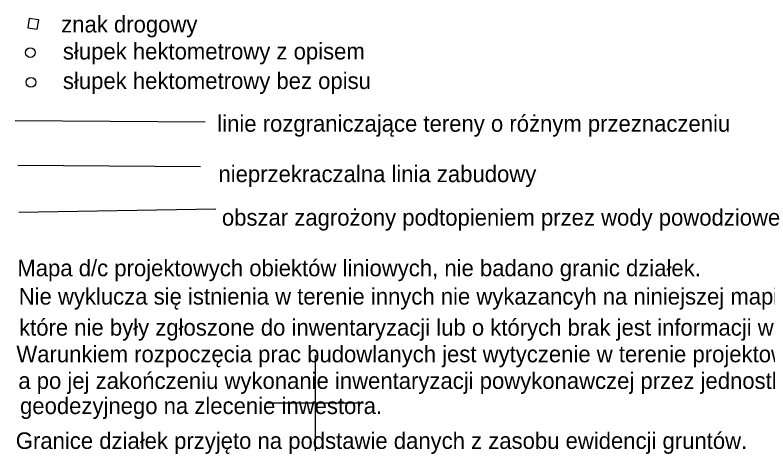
# Model space of a CAD drawing. Extents: x 6596400 to 6597200, y 5539751 to 5540251.
# Drawn here: x 6596634.31 to 6596673.62, y 5540048.34 to 5540071.24 of the extents above; entities that cross this region are included whole.
import ezdxf

# ---------------------------------------------------------------- set-up
doc = ezdxf.new("R2010")
doc.units = 0
for name, color, linetype in [('996-Tekst dodatkowy mały', 7, 'Continuous'), ('Linia obszaru zagospodarowania terenu', 7, 'Continuous'), ('Nieprzekraczalna linia zabudowy', 7, 'Continuous'), ('Strefa korytarza ekologicznego', 7, 'Continuous'), ('Wstawianie ramki sekcyjnej z opisem', 7, 'Continuous'), ('właz do komory lub kanału - kwadratowy', 7, 'Continuous'), ('właz do komory lub kanału - okrągły', 7, 'Continuous')]:
    doc.layers.add(name, color=color, linetype=linetype)

# ---------------------------------------------------------------- blocks, each defined once
blk = doc.blocks.new('RAMKA500K')
for p, q in [((250, 48.5), (250, 53.5)), ((247.5, 51), (252.5, 51))]:
    blk.add_line(p, q)
blk = doc.blocks.new('US22A')
blk.add_lwpolyline([(-0.25, -0.25), (0.25, -0.25), (0.25, 0.25), (-0.25, 0.25)], close=True)
blk = doc.blocks.new('US22')
blk.add_circle((0, 0), 0.25)

msp = doc.modelspace()

# ---------------------------------------------------------------- linework, layer by layer
at = {"layer": 'Linia obszaru zagospodarowania terenu'}
msp.add_lwpolyline([(6596634.31, 5540065.74), (6596644.23, 5540065.66)], dxfattribs=at)
at = {"layer": 'Nieprzekraczalna linia zabudowy'}
msp.add_lwpolyline([(6596634.45, 5540063.4), (6596644, 5540063.33)], dxfattribs=at)
at = {"layer": 'Strefa korytarza ekologicznego'}
msp.add_lwpolyline([(6596634.51, 5540060.96), (6596644.8, 5540061.12)], dxfattribs=at)

# ---------------------------------------------------------------- block references
at = {"layer": 'Wstawianie ramki sekcyjnej z opisem'}
msp.add_blockref('RAMKA500K', (6596400, 5540000), dxfattribs=at)
at = {"layer": 'właz do komory lub kanału - kwadratowy', "rotation": -8.97300000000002}
msp.add_blockref('US22A', (6596635.26, 5540070.78), dxfattribs=at)
at = {"layer": 'właz do komory lub kanału - okrągły'}
for p in [(6596635.11, 5540069.28), (6596635.14, 5540067.73)]:
    msp.add_blockref('US22', p, dxfattribs=at)

# ---------------------------------------------------------------- texts
at = {"layer": '996-Tekst dodatkowy mały'}
for s, p in [('znak drogowy', (6596636.72, 5540070.33)), ('słupek hektometrowy z opisem', (6596636.81, 5540068.92)), ('słupek hektometrowy bez opisu', (6596636.81, 5540067.38)), ('linie rozgraniczające tereny o różnym przeznaczeniu', (6596644.87, 5540065.15)), ('nieprzekraczalna linia zabudowy', (6596644.93, 5540062.52)), ('obszar zagrożony podtopieniem przez wody powodziowe', (6596645.11, 5540060.25)), ('Mapa d/c projektowych obiektów liniowych, nie badano granic działek.', (6596634.43, 5540057.61)), ('Nie wyklucza się istnienia w terenie innych nie wykazancyh na niniejszej mapie urządzeń podziemnych,', (6596634.5, 5540056.13)), ('które nie były zgłoszone do inwentaryzacji lub o których brak jest informacji w instytucjach branżowych.', (6596634.52, 5540054.51)), ('Warunkiem rozpoczęcia prac budowlanych jest wytyczenie w terenie projektowanej budowli,', (6596634.38, 5540053.12)), ('a po jej zakończeniu wykonanie inwentaryzacji powykonawczej przez jednostke wykonawstwa', (6596634.48, 5540051.73)), ('geodezyjnego na zlecenie inwestora.', (6596634.57, 5540050.42)), ('Granice działek przyjęto na podstawie danych z zasobu ewidencji gruntów.', (6596634.35, 5540048.6))]:
    msp.add_text(s, height=0.862, dxfattribs=at).set_placement(p)

doc.saveas('drawing.dxf')
